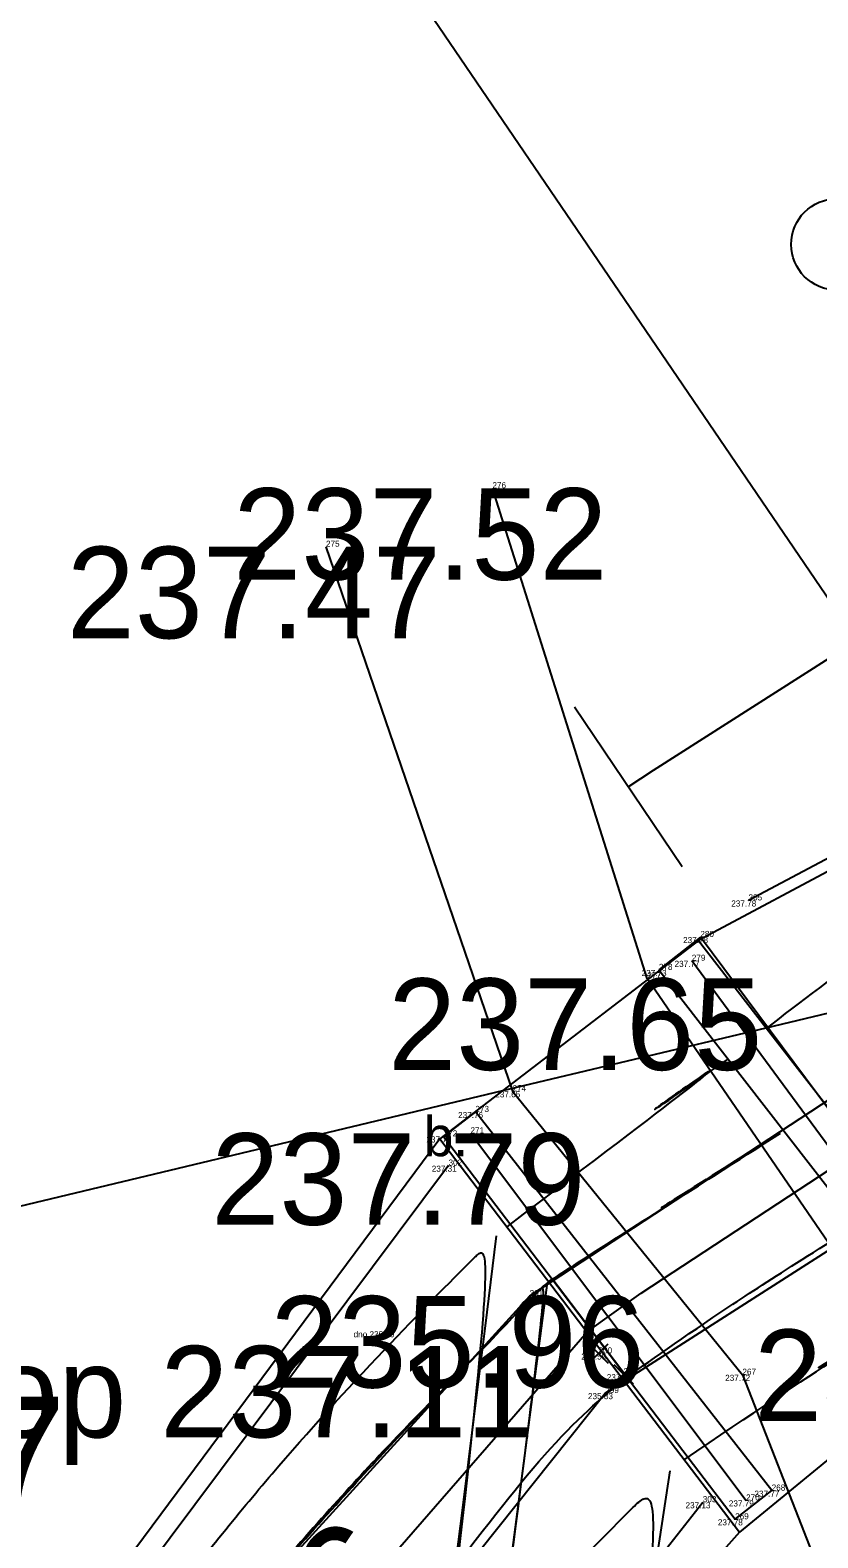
# Model space of a CAD drawing. Extents: x -555757 to -553364, y -1100723 to -1096439.
# Drawn here: x -554313.94 to -554301.02, y -1100453.09 to -1100428.37 of the extents above; entities that cross this region are included whole.
import ezdxf

# ---------------------------------------------------------------- set-up
doc = ezdxf.new("R2010")
doc.units = 0
for name, color, linetype in [('00_NÁVRH - 0.18 mm', 7, 'Continuous'), ('00_NÁVRH - 0.35 mm', 7, 'Continuous'), ('00_NÁVRH - Řezy', 7, 'Continuous'), ('01_HLADINA', 7, 'Continuous'), ('C$SLO$PARCELY', 7, 'Continuous'), ('Geodet. výšky - netisknuté', 7, 'Continuous'), ('HRANA$SVAHU', 7, 'Continuous'), ('HRANICE$PARCELY', 7, 'Continuous'), ('HRANICE$POROSTU', 7, 'Continuous'), ('OSA$KOLEJI', 7, 'Continuous'), ('POPIS', 7, 'Continuous'), ('POPIS$POVRCHU', 7, 'Continuous'), ('ROZHRANI', 7, 'Continuous'), ('SLOUPY', 7, 'Continuous'), ('SLUCKOV$$C$RA', 7, 'Continuous'), ('SVODIDLA', 7, 'Continuous'), ('VOZOVKA', 7, 'Continuous'), ('VYSKA_PODR_BOD', 7, 'Continuous')]:
    doc.layers.add(name, color=color, linetype=linetype)

# ---------------------------------------------------------------- blocks, each defined once
blk = doc.blocks.new('POINT_DISPLAY')
blk.add_line((0, 0), (0, 0))
blk = doc.blocks.new('1$01')
at = {"layer": 'SLOUPY'}
for radius in [0.75, 0.032]:
    blk.add_circle((0, 0), radius, dxfattribs=at)
blk = doc.blocks.new('BOD')
at = {"layer": 'POPIS'}
for p, q in [((-0.283, -0.283), (0.283, 0.283)), ((-0.283, 0.283), (0.283, -0.283))]:
    blk.add_line(p, q, dxfattribs=at)

msp = doc.modelspace()

# ---------------------------------------------------------------- linework, layer by layer
at = {"layer": '00_NÁVRH - 0.18 mm'}
msp.add_line((-554303.25, -1100442.087), (-554305.013, -1100439.469), dxfattribs=at)
for points in [[(-554304.132, -1100440.778), (-554303.717, -1100440.506), (-554294.09, -1100434.353), (-554293.139, -1100433.684), (-554282.239, -1100425.43), (-554259.446, -1100410.384), (-554237.051, -1100386.392), (-554219.344, -1100365.551), (-554201.444, -1100345.593), (-554181.456, -1100321.949), (-554167.529, -1100306.106), (-554158.736, -1100292.844), (-554155.424, -1100286.982), (-554151.899, -1100276.102), (-554149.815, -1100266.172), (-554147.888, -1100248.912), (-554145.412, -1100226.73), (-554144.647, -1100201.003), (-554144.901, -1100190.118), (-554147.4, -1100181.478), (-554150.404, -1100169.828), (-554154.061, -1100160.312), (-554156.787, -1100155.911), (-554161.244, -1100148.916)], [(-554315.472, -1100482.811), (-554315.568, -1100470.17), (-554315.906, -1100465.362), (-554315.906, -1100462.928), (-554315.637, -1100462.143), (-554315.555, -1100462.061), (-554311.316, -1100457.202), (-554304.809, -1100449.717), (-554303.919, -1100449.079), (-554299.613, -1100446.257), (-554289.985, -1100440.104), (-554289.035, -1100439.435), (-554278.134, -1100431.181), (-554255.342, -1100416.134), (-554232.947, -1100392.143), (-554215.24, -1100371.301), (-554197.34, -1100351.344), (-554177.352, -1100327.7), (-554163.425, -1100311.857)]]:
    msp.add_lwpolyline(points, dxfattribs=at)
for points in [[(-554301.845, -1100444.725), (-554300.846, -1100443.939), (-554298.008, -1100441.867), (-554281.284, -1100430.604), (-554273.473, -1100425.505), (-554270.54, -1100423.598), (-554266.624, -1100421.067), (-554264.034, -1100419.37), (-554263.022, -1100418.684), (-554261.448, -1100417.503), (-554259.471, -1100416.134), (-554258.272, -1100415.281), (-554256.845, -1100414.262), (-554256.324, -1100413.755), (-554247.895, -1100404.563), (-554238.125, -1100393.334), (-554236.842, -1100391.714), (-554222.711, -1100375.934), (-554213.157, -1100365.116), (-554201.883, -1100352.505), (-554188.814, -1100337.586), (-554183.238, -1100330.947), (-554177.835, -1100324.312), (-554168.384, -1100313.813), (-554165.141, -1100310.341), (-554161.497, -1100305.373), (-554157.209, -1100299.655), (-554153.93, -1100295.132), (-554151.942, -1100292.185), (-554149.85, -1100287.656), (-554147.565, -1100282.51), (-554146.241, -1100279.727), (-554145.674, -1100278.484), (-554145.323, -1100277.043), (-554144.927, -1100274.518), (-554144.058, -1100268.792), (-554143.081, -1100262.492), (-554142.168, -1100256.516), (-554140.01, -1100242.36), (-554138.06, -1100229.56), (-554137.586, -1100222.304), (-554137.112, -1100215.048), (-554137.273, -1100209.483), (-554137.522, -1100200.879), (-554137.73, -1100193.685), (-554137.856, -1100189.315), (-554137.891, -1100188.103), (-554137.904, -1100187.596), (-554137.909, -1100187.291), (-554137.945, -1100186.71), (-554138.083, -1100186.325), (-554138.949, -1100184.134), (-554141.636, -1100177.271), (-554143.477, -1100172.646), (-554149.023, -1100158.582), (-554152.817, -1100152.326), (-554156.44, -1100146.42), (-554301.347, -1100444.33), (-554154.649, -1100149.385)], [(-554314.417, -1100513.988), (-554314.582, -1100513.749), (-554314.935, -1100513.181), (-554315.384, -1100511.726), (-554316.281, -1100506.604), (-554316.377, -1100505.57), (-554316.456, -1100503.941), (-554316.566, -1100500.746), (-554316.659, -1100497.74), (-554316.762, -1100493.317), (-554316.913, -1100488.501), (-554317.002, -1100484.644), (-554317.257, -1100477.919), (-554317.382, -1100473.141), (-554317.442, -1100469.848), (-554317.606, -1100466.831), (-554317.722, -1100464.81), (-554317.805, -1100463.233), (-554317.759, -1100462.426), (-554316.795, -1100460.405), (-554314.574, -1100457.619), (-554311.478, -1100453.9), (-554309.939, -1100451.947), (-554307.949, -1100449.799), (-554306.455, -1100448.289), (-554306.121, -1100447.993), (-554314.5, -1100513.869), (-554306.291, -1100448.139)], [(-554311.86, -1100511.938), (-554312.434, -1100509.94), (-554313.024, -1100507.015), (-554313.36, -1100504.824), (-554313.477, -1100502.343), (-554313.592, -1100499.092), (-554313.64, -1100493.221), (-554313.549, -1100489.959), (-554313.549, -1100484.214), (-554313.549, -1100477.597), (-554313.714, -1100471.542), (-554313.882, -1100467.25), (-554313.923, -1100465.45), (-554313.767, -1100464.089), (-554312.685, -1100462.214), (-554309.214, -1100458.206), (-554306.593, -1100455.182), (-554303.675, -1100452.188), (-554303.213, -1100451.814), (-554312.278, -1100510.987), (-554303.447, -1100451.997)]]:
    msp.add_open_spline(points, degree=3, dxfattribs=at)
at = {"layer": '00_NÁVRH - 0.35 mm'}
for points in [[(-554306.121, -1100447.993), (-554303.145, -1100445.739), (-554301.845, -1100444.726), (-554304.705, -1100446.777), (-554302.49, -1100445.238)], [(-554305.437, -1100448.893), (-554304.805, -1100448.477), (-554302.369, -1100446.933), (-554300.903, -1100445.978), (-554305.14, -1100448.658), (-554301.634, -1100446.458)], [(-554304.209, -1100450.506), (-554304.008, -1100450.352), (-554302.624, -1100449.377), (-554301.199, -1100448.473), (-554299.696, -1100447.536)], [(-554313.952, -1100513.615), (-554313.958, -1100513.608), (-554314.479, -1100512.835), (-554314.851, -1100511.368), (-554315.085, -1100510.042), (-554315.469, -1100507.851), (-554315.769, -1100506.129), (-554315.816, -1100505.705), (-554315.847, -1100504.963), (-554315.974, -1100501.578), (-554316.005, -1100498.962), (-554316.1, -1100495.84), (-554316.131, -1100492.846), (-554316.249, -1100488.998), (-554316.401, -1100481.419), (-554316.527, -1100473.073), (-554316.625, -1100469.789), (-554316.956, -1100464.389), (-554316.87, -1100462.539), (-554316.374, -1100461.233), (-554314.939, -1100459.29), (-554312.44, -1100456.572), (-554309.696, -1100453.384), (-554307.571, -1100451.07), (-554306.062, -1100449.51), (-554305.473, -1100448.922), (-554305.437, -1100448.893), (-554313.955, -1100513.612), (-554305.455, -1100448.907)], [(-554303.213, -1100451.814), (-554300.984, -1100450.289), (-554298.644, -1100448.894), (-554302.148, -1100450.984), (-554299.821, -1100449.58)], [(-554312.363, -1100512.342), (-554312.368, -1100512.333), (-554312.623, -1100511.834), (-554312.839, -1100510.653), (-554313.388, -1100508.394), (-554314.085, -1100505.395), (-554314.208, -1100501.825), (-554314.497, -1100495.645), (-554314.475, -1100486.499), (-554314.473, -1100475.881), (-554314.602, -1100468.426), (-554314.862, -1100464.792), (-554314.485, -1100462.214), (-554311.756, -1100459.401), (-554309.164, -1100456.443), (-554306.736, -1100453.248), (-554305.198, -1100451.285), (-554304.284, -1100450.563), (-554304.209, -1100450.506)]]:
    msp.add_open_spline(points, degree=3, dxfattribs=at)
at = {"layer": '00_NÁVRH - Řezy'}
msp.add_line((-554311.648, -1100421.829), (-554289.026, -1100455.062), dxfattribs=at)
at = {"layer": '01_HLADINA'}
msp.add_line((-554304.152, -1100450.462), (-554305.38, -1100448.849), dxfattribs=at)
for points, degree in [([(-554305.437, -1100448.893), (-554305.449, -1100448.902), (-554305.676, -1100449.085), (-554306.358, -1100449.849), (-554307.811, -1100451.286), (-554309.955, -1100453.63), (-554312.283, -1100456.485), (-554314.683, -1100458.94), (-554316.289, -1100460.883), (-554317.008, -1100462.669), (-554316.964, -1100464.518), (-554316.879, -1100465.878), (-554316.828, -1100466.617)], 3), ([(-554305.38, -1100448.849), (-554305.399, -1100448.863), (-554305.418, -1100448.878), (-554305.437, -1100448.893)], 2), ([(-554314.719, -1100466.971), (-554314.728, -1100466.819), (-554314.774, -1100466.022), (-554314.862, -1100464.792), (-554314.485, -1100462.214), (-554311.756, -1100459.401), (-554309.164, -1100456.443), (-554306.736, -1100453.248), (-554305.198, -1100451.285), (-554304.284, -1100450.563), (-554304.209, -1100450.506)], 3), ([(-554304.209, -1100450.506), (-554304.19, -1100450.491), (-554304.171, -1100450.477), (-554304.152, -1100450.462)], 2)]:
    msp.add_open_spline(points, degree=degree, dxfattribs=at)
at = {"layer": 'HRANA$SVAHU'}
for p, q in [((-554292.04, -1100437.26), (-554302.16, -1100442.64)), ((-554290.63, -1100439.2), (-554305.75, -1100449.13)), ((-554304.51, -1100450.72), (-554289.33, -1100441)), ((-554307.08, -1100446.99), (-554317.08, -1100460.36)), ((-554305.75, -1100449.13), (-554316.9, -1100461.37)), ((-554314.58, -1100463.34), (-554304.51, -1100450.72)), ((-554313.24, -1100465.64), (-554302.91, -1100452.51))]:
    msp.add_line(p, q, dxfattribs=at)
at = {"layer": 'HRANICE$PARCELY'}
msp.add_line((-554315.82, -1100448.06), (-554306.19, -1100445.76), dxfattribs=at)
for points in [[(-554162.09, -1100134.23), (-554156.55, -1100150.03), (-554146.24, -1100167.08), (-554138.32, -1100193.47), (-554137.96, -1100207.15), (-554143.4, -1100261.37), (-554146.27, -1100275.63), (-554152.99, -1100291.23), (-554164.48, -1100308.32), (-554187.58, -1100335.96), (-554210.63, -1100360.69), (-554227.58, -1100380.8), (-554247.9, -1100404.32), (-554263, -1100418.66), (-554290.96, -1100436.86), (-554302.98, -1100443.3), (-554306.19, -1100445.76)], [(-554282.42, -1100440.07), (-554284.43, -1100441.09), (-554298.12, -1100449.57), (-554302.31, -1100453), (-554314.45, -1100466.67)], [(-554306.19, -1100445.76), (-554301.87, -1100444.73), (-554282.42, -1100440.07)], [(-554306.19, -1100445.76), (-554307.22, -1100446.55), (-554316.95, -1100459.64), (-554317.61, -1100459.96)]]:
    msp.add_lwpolyline(points, dxfattribs=at)
at = {"layer": 'ROZHRANI'}
for p, q in [((-554302.95, -1100443.24), (-554303.63, -1100443.78)), ((-554298.07, -1100449.8), (-554302.95, -1100443.24)), ((-554303.63, -1100443.78), (-554298.71, -1100450.12)), ((-554306.64, -1100446.11), (-554307.16, -1100446.51)), ((-554301.78, -1100452.32), (-554306.64, -1100446.11)), ((-554307.16, -1100446.51), (-554302.38, -1100452.79)), ((-554302.38, -1100452.79), (-554301.78, -1100452.32))]:
    msp.add_line(p, q, dxfattribs=at)
at = {"layer": 'SLUCKOV$$C$RA'}
for p, q in [((-554302.98, -1100443.3), (-554301.87, -1100444.73)), ((-554301.87, -1100444.73), (-554298.12, -1100449.57)), ((-554307.22, -1100446.55), (-554302.31, -1100453))]:
    msp.add_line(p, q, dxfattribs=at)
at = {"layer": 'SVODIDLA'}
for p, q in [((-554298.57, -1100449.77), (-554303.09, -1100443.63)), ((-554306.72, -1100446.46), (-554302.2, -1100452.48))]:
    msp.add_line(p, q, dxfattribs=at)
at = {"layer": 'VOZOVKA'}
for p, q in [((-554303.82, -1100443.92), (-554306.36, -1100435.88)), ((-554309.09, -1100436.84), (-554306.03, -1100445.77)), ((-554299.14, -1100450.76), (-554303.82, -1100443.92)), ((-554306.03, -1100445.77), (-554302.26, -1100450.42)), ((-554302.26, -1100450.42), (-554301.06, -1100453.48))]:
    msp.add_line(p, q, dxfattribs=at)

# ---------------------------------------------------------------- block references
at = {"layer": 'HRANICE$POROSTU'}
msp.add_blockref('1$01', (-554300.71, -1100431.88), dxfattribs=at)
at = {"layer": 'POPIS', "xscale": 0.5624965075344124, "yscale": 0.5624965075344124}
for p in [(-554304.62, -1100450.07), (-554304.21, -1100450.41)]:
    msp.add_blockref('BOD', p, dxfattribs=at)
at = {"layer": 'ROZHRANI'}
for p in [(-554306.36, -1100435.88), (-554309.09, -1100436.84), (-554302.16, -1100442.64), (-554302.95, -1100443.24), (-554303.63, -1100443.78), (-554303.09, -1100443.63), (-554303.82, -1100443.92), (-554306.03, -1100445.77), (-554306.64, -1100446.11), (-554307.16, -1100446.51), (-554306.72, -1100446.46), (-554307.08, -1100446.99), (-554305.75, -1100449.13), (-554304.62, -1100450.07), (-554304.21, -1100450.41), (-554302.26, -1100450.42), (-554304.51, -1100450.72), (-554302.91, -1100452.51), (-554302.2, -1100452.48), (-554301.78, -1100452.32), (-554302.38, -1100452.79)]:
    msp.add_blockref('POINT_DISPLAY', p, dxfattribs=at)

# ---------------------------------------------------------------- texts
at = {"layer": 'C$SLO$PARCELY'}
msp.add_text('2587', height=2, dxfattribs=at).set_placement((-554319.299, -1100452.78))
msp.add_text('2586', height=2, rotation=45, dxfattribs=at).set_placement((-554311.582, -1100458.23))
at = {"layer": 'Geodet. výšky - netisknuté'}
for s, p in [('237.78', (-554302.443, -1100442.74)), ('237.78', (-554303.233, -1100443.34)), ('237.73', (-554303.913, -1100443.88)), ('237.77', (-554303.373, -1100443.73)), ('237.65', (-554306.313, -1100445.87)), ('237.76', (-554306.923, -1100446.21)), ('237.77', (-554307.443, -1100446.61)), ('237.31', (-554307.355, -1100447.09)), ('dno 235.59', (-554308.636, -1100449.805)), ('235.59', (-554304.903, -1100450.17)), ('237.11', (-554304.485, -1100450.51)), ('237.72', (-554302.543, -1100450.52)), ('235.83', (-554304.793, -1100450.82)), ('237.13', (-554303.193, -1100452.61)), ('237.79', (-554302.483, -1100452.58)), ('237.77', (-554302.063, -1100452.42)), ('237.78', (-554302.663, -1100452.89))]:
    msp.add_text(s, height=0.1, dxfattribs=at).set_placement(p)
at = {"layer": 'OSA$KOLEJI'}
for s, p in [('276', (-554306.36, -1100435.88)), ('275', (-554309.09, -1100436.84)), ('305', (-554302.16, -1100442.64)), ('280', (-554302.95, -1100443.24)), ('279', (-554303.09, -1100443.63)), ('277', (-554303.82, -1100443.92)), ('278', (-554303.63, -1100443.78)), ('274', (-554306.03, -1100445.77)), ('273', (-554306.64, -1100446.11)), ('272', (-554307.16, -1100446.51)), ('271', (-554306.72, -1100446.46)), ('302', (-554307.08, -1100446.99)), ('301', (-554305.75, -1100449.13)), ('300', (-554304.62, -1100450.07)), ('298', (-554304.21, -1100450.41)), ('267', (-554302.26, -1100450.42)), ('299', (-554304.51, -1100450.72)), ('268', (-554301.78, -1100452.32)), ('303', (-554302.91, -1100452.51)), ('270', (-554302.2, -1100452.48)), ('269', (-554302.38, -1100452.79))]:
    msp.add_text(s, height=0.1, dxfattribs=at).set_placement(p)
at = {"layer": 'POPIS'}
msp.add_text('strop 237.11', height=1.5, dxfattribs=at).set_placement((-554316.823, -1100451.447))
at = {"layer": 'POPIS$POVRCHU'}
msp.add_text('b.', height=0.65, dxfattribs=at).set_placement((-554307.485, -1100446.835))
at = {"layer": 'VYSKA_PODR_BOD'}
for s, p in [('237.52', (-554310.61, -1100437.38)), ('237.47', (-554313.34, -1100438.34)), ('237.65', (-554308.07, -1100445.42)), ('237.79', (-554310.97, -1100447.96)), ('235.96', (-554310, -1100450.63)), ('237.79', (-554302.07, -1100451.18))]:
    msp.add_text(s, height=1.5, dxfattribs=at).set_placement(p)

doc.saveas('drawing.dxf')
